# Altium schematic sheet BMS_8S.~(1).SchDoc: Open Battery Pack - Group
size A3; Author: Morgane Vallée; Revision: 1.0; SheetNumber: 2; SheetTotal: 3
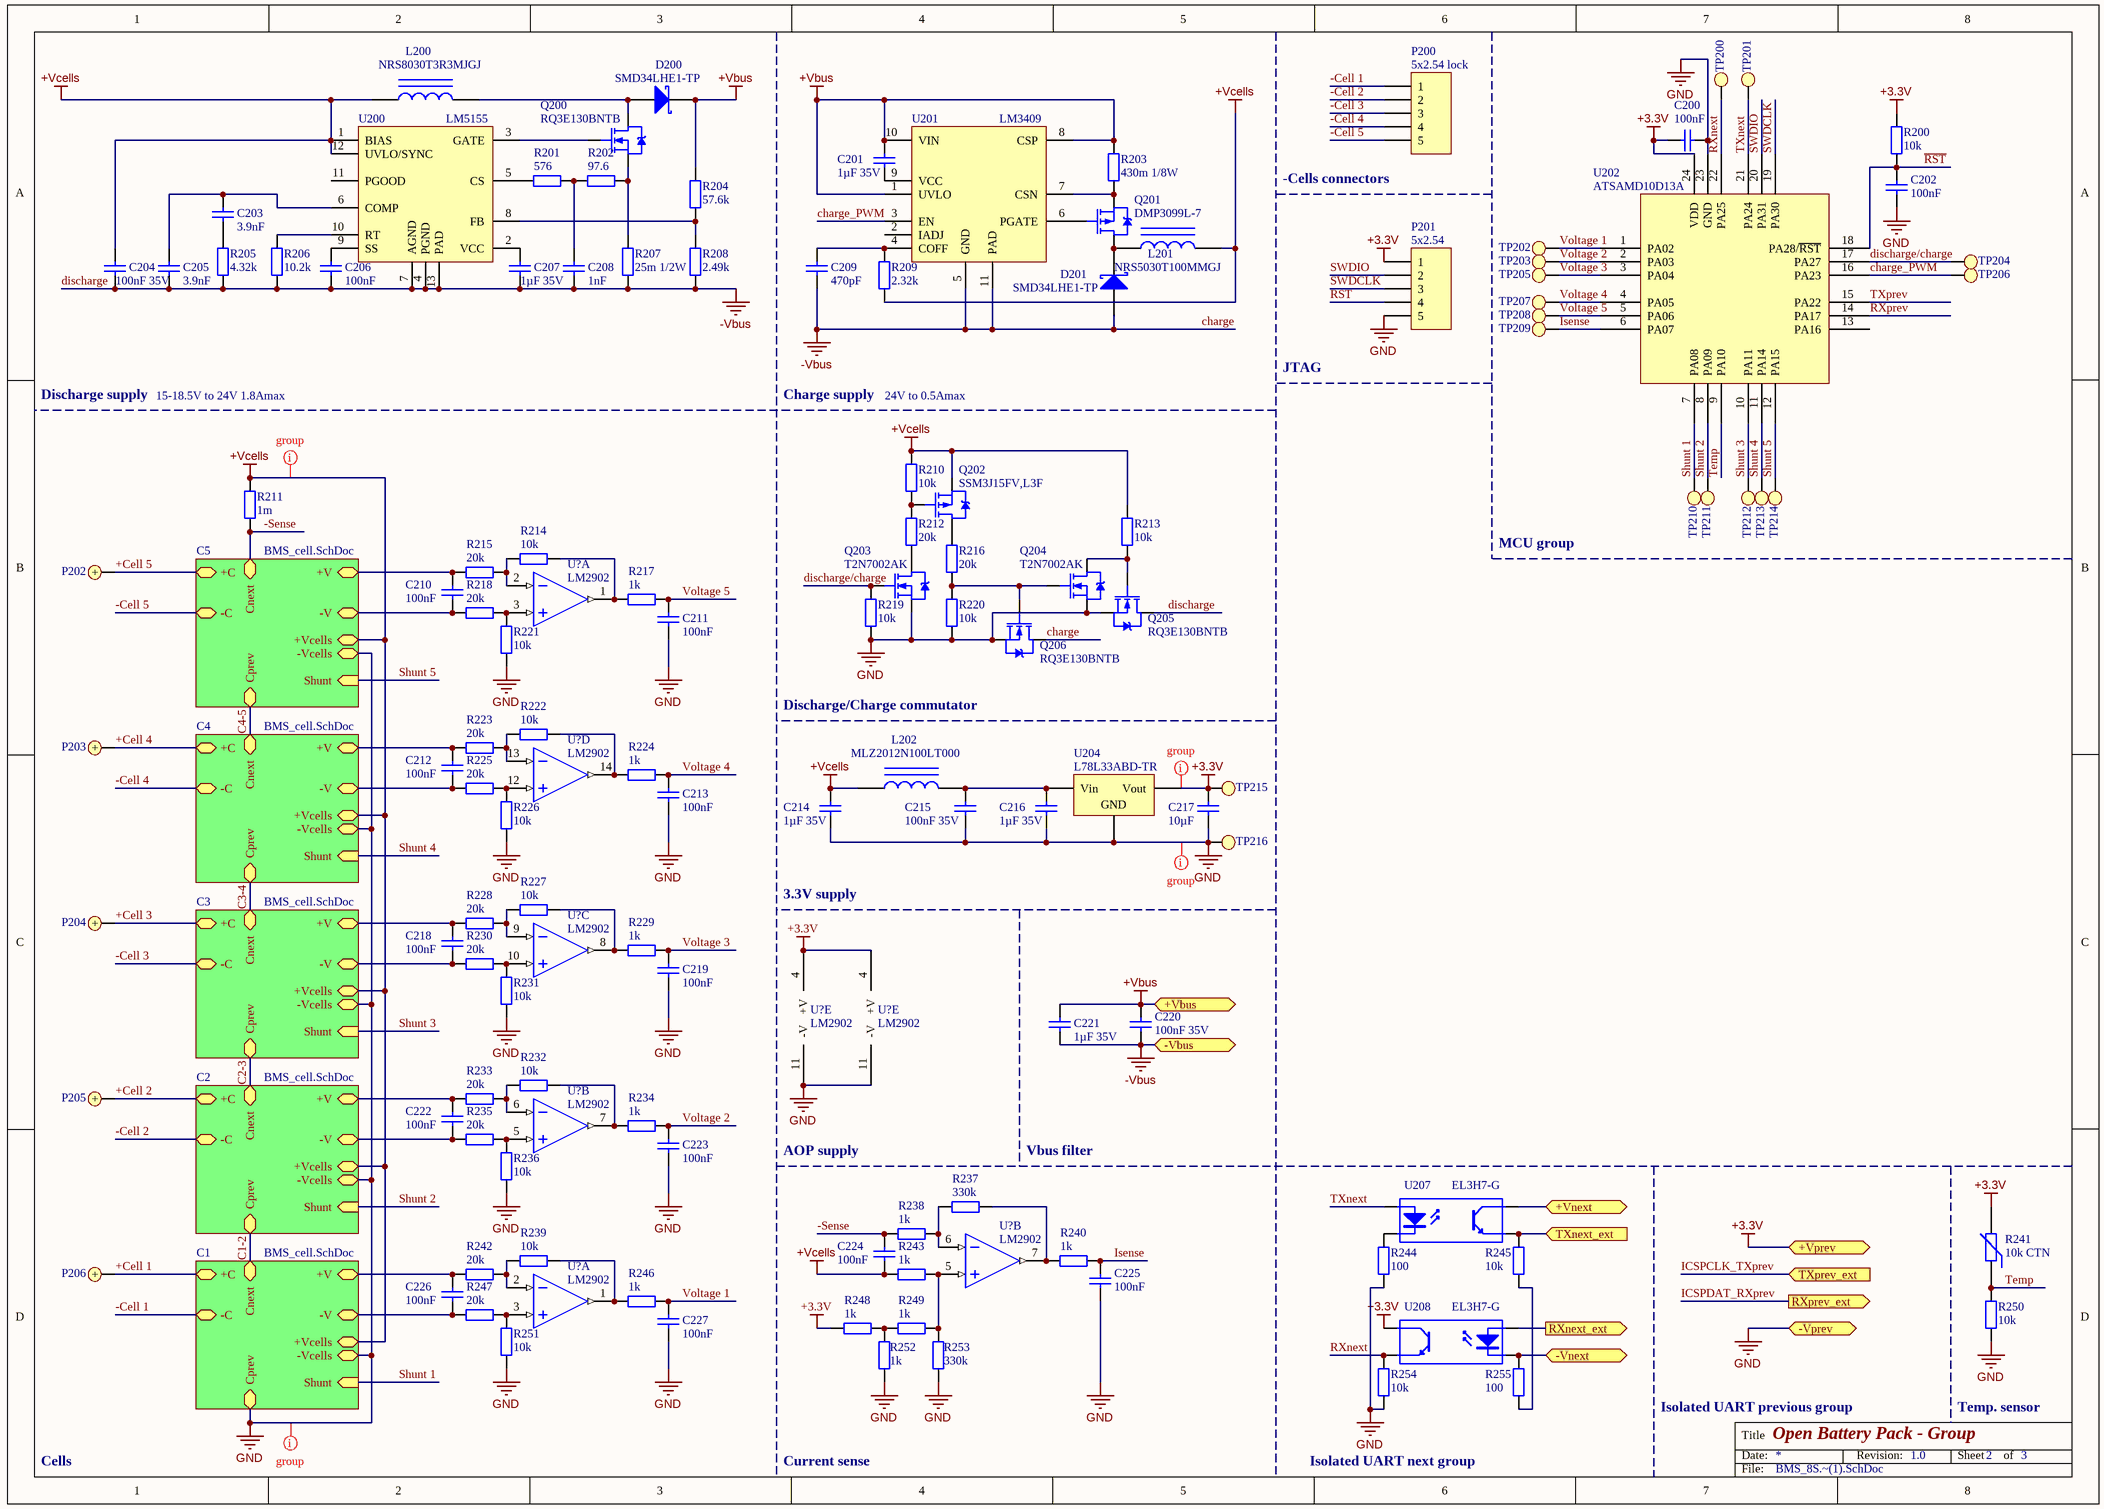
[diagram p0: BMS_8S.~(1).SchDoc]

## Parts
(Parts that share a designator on the sheet are numbered #1, #2 ... from top to bottom, then left to right.)
C200  100nF  [C0603]
C201  1µF 35V  [C0805]
C202  100nF  [C0603]
C203  3.9nF  [C0603]
C204  100nF 35V  [C0603]
C205  3.9nF  [C0603]
C206  100nF  [C0603]
C207  1µF 35V  [C0805]
C208  1nF  [C0603]
C209  470pF  [C0603]
C210  100nF  [C0603]
C211  100nF  [C0603]
C212  100nF  [C0603]
C213  100nF  [C0603]
C214  1µF 35V  [C0805]
C215  100nF 35V  [C0603]
C216  1µF 35V  [C0805]
C217  10µF  [C0603]
C218  100nF  [C0603]
C219  100nF  [C0603]
C220  100nF 35V  [C0603]
C221  1µF 35V  [C0805]
C222  100nF  [C0603]
C223  100nF  [C0603]
C224  100nF  [C0603]
C225  100nF  [C0603]
C226  100nF  [C0603]
C227  100nF  [C0603]
D200  SMD34LHE1-TP  [SOD-123H]
D201  SMD34LHE1-TP  [SOD-123H]
L200  NRS8030T3R3MJGJ  [SELF_SMD_8x8]
L201  NRS5030T100MMGJ  [SELF_SMD_4.9x4.9]
L202  MLZ2012N100LT000  [FER 0805/2012]
P200  5x2.54 lock  [MOLEX KK 0022272051]
P201  5x2.54  [HDR1X5]
P202  Bat+  [Keystone 241]  (value not drawn)
P203  Bat+  [Keystone 241]  (value not drawn)
P204  Bat+  [Keystone 241]  (value not drawn)
P205  Bat+  [Keystone 241]  (value not drawn)
P206  Bat+  [Keystone 241]  (value not drawn)
Q200  RQ3E130BNTB  [INFINEON PG-TSDSON-8]
Q201  DMP3099L-7  [DIODES SOT-23-3]
Q202  SSM3J15FV,L3F  [DIODES SOT-23-3]
Q203  T2N7002AK  [DIODES SOT-23-3]
Q204  T2N7002AK  [DIODES SOT-23-3]
Q205  RQ3E130BNTB  [INFINEON PG-TSDSON-8]
Q206  RQ3E130BNTB  [INFINEON PG-TSDSON-8]
R200  10k  [R0603]
R201  576  [R0603]
R202  97.6  [R0603]
R203  430m 1/8W  [R0603]
R204  57.6k  [R0603]
R205  4.32k  [R0603]
R206  10.2k  [R0603]
R207  25m 1/2W  [R1206]
R208  2.49k  [R0603]
R209  2.32k  [R0603]
R210  10k  [R0603]
R211  1m  [R1206]
R212  20k  [R0603]
R213  10k  [R0603]
R214  10k  [R0603]
R215  20k  [R0603]
R216  20k  [R0603]
R217  1k  [R0603]
R218  20k  [R0603]
R219  10k  [R0603]
R220  10k  [R0603]
R221  10k  [R0603]
R222  10k  [R0603]
R223  20k  [R0603]
R224  1k  [R0603]
R225  20k  [R0603]
R226  10k  [R0603]
R227  10k  [R0603]
R228  20k  [R0603]
R229  1k  [R0603]
R230  20k  [R0603]
R231  10k  [R0603]
R232  10k  [R0603]
R233  20k  [R0603]
R234  1k  [R0603]
R235  20k  [R0603]
R236  10k  [R0603]
R237  330k  [R0603]
R238  1k  [R0603]
R239  10k  [R0603]
R240  1k  [R0603]
R241  10k CTN  [NTC 0402/1005]
R242  20k  [R0603]
R243  1k  [R0603]
R244  100  [R0603]
R245  10k  [R0603]
R246  1k  [R0603]
R247  20k  [R0603]
R248  1k  [R0603]
R249  1k  [R0603]
R250  10k  [R0603]
R251  10k  [R0603]
R252  1k  [R0603]
R253  330k  [R0603]
R254  10k  [R0603]
R255  100  [R0603]
TP200  Test Point  [Test Point]  (value not drawn)
TP201  Test Point  [Test Point]  (value not drawn)
TP202  Test Point  [Test Point]  (value not drawn)
TP203  Test Point  [Test Point]  (value not drawn)
TP204  Test Point  [Test Point]  (value not drawn)
TP205  Test Point  [Test Point]  (value not drawn)
TP206  Test Point  [Test Point]  (value not drawn)
TP207  Test Point  [Test Point]  (value not drawn)
TP208  Test Point  [Test Point]  (value not drawn)
TP209  Test Point  [Test Point]  (value not drawn)
TP210  Test Point  [Test Point]  (value not drawn)
TP211  Test Point  [Test Point]  (value not drawn)
TP212  Test Point  [Test Point]  (value not drawn)
TP213  Test Point  [Test Point]  (value not drawn)
TP214  Test Point  [Test Point]  (value not drawn)
TP215  Test Point  [Test Point]  (value not drawn)
TP216  Test Point  [Test Point]  (value not drawn)
U200  LM5155  [TI WSON-12]
U201  LM3409  [TI MSOP-10 DGQ]
U202  ATSAMD10D13A  [SMSC QFN-24 4x4MM]
U204  L78L33ABD-TR  [ST SOIC-8N]
U207  EL3H7-G  [OPTO_EL3H7-G]
U208  EL3H7-G  [OPTO_EL3H7-G]
U?#1  LM2902  [Atmel SO-14 14S1]  (part A of 5)
U?#2  LM2902  [Atmel SO-14 14S1]  (part D of 5)
U?#3  LM2902  [Atmel SO-14 14S1]  (part C of 5)
U?#4  LM2902  [Atmel SO-14 14S1]  (part E of 5)
U?#5  LM2902  [Atmel SO-14 14S1]  (part E of 5)
U?#6  LM2902  [Atmel SO-14 14S1]  (part B of 5)
U?#7  LM2902  [Atmel SO-14 14S1]  (part B of 5)
U?#8  LM2902  [Atmel SO-14 14S1]  (part A of 5)

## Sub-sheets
C1 = BMS_cell.SchDoc: -C, -V, +C, +Vcells, Cnext, -Vcells, +V, Shunt (in), Cprev
C2 = BMS_cell.SchDoc: -C, -V, +C, +Vcells, Cnext, -Vcells, +V, Shunt (in), Cprev
C3 = BMS_cell.SchDoc: -C, -V, +C, +Vcells, Cnext, -Vcells, +V, Shunt (in), Cprev
C4 = BMS_cell.SchDoc: -C, -V, +C, +Vcells, Cnext, -Vcells, +V, Shunt (in), Cprev
C5 = BMS_cell.SchDoc: -C, -V, +C, +Vcells, Cnext, -Vcells, +V, Shunt (in), Cprev

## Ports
+Vbus, +Vnext, +Vprev, -Vbus, -Vnext, -Vprev, RXnext_ext (out), RXprev_ext (out), TXnext_ext (in), TXprev_ext (in)

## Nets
+3.3V: C200.2 C217.1 P201.1 R200.2 R241.2 R248.2 TP215.1 U202.24(VDD) U204.3(Vout) U208.4(C) U?#4.4(+V) U?#5.4(+V) ; port +Vprev
+Vbus: C201.1 C220.1 C221.1 D200.3(K) R203.2 R204.2 U201.1(UVLO) U201.8(CSP) U201.10(VIN) ; port +Vbus
+Vcells: C204.1 C214.1 C224.2 L200.1 L201.2 L202.1 Q202.2(S) R209.2 R210.2 R211.2 R213.2 R243.2 U200.1(BIAS) U200.12(UVLO/SYNC) ; sheet C1/+Vcells, sheet C2/+Vcells, sheet C3/+Vcells, sheet C4/+Vcells, sheet C5/+Vcells
charge: C204.2 C205.2 C206.2 C207.2 C208.2 C209.2 C220.2 C221.2 D201.1(A) Q205.3(D) Q206.3(D) R205.1 R206.1 R207.1 R208.1 U200.4(PGND) U200.7(AGND) U200.13(PAD) U201.5(GND) U201.11(PAD) ; port -Vbus  [also labelled -Vbus, discharge]
GND: C200.1 C202.1 C211.2 C213.2 C214.2 C215.2 C216.2 C217.2 C219.2 C223.2 C225.2 C227.2 P201.5 Q203.2(S) Q204.2(S) Q205.2(S) Q206.2(S) R219.1 R220.1 R221.2 R226.2 R231.2 R236.2 R244.1 R250.2 R251.2 R252.2 R253.1 R254.1 TP216.1 U202.23(GND) U204.2(GND) U?#4.11(-V) U?#5.11(-V) ; port -Vprev, sheet C1/-Vcells, sheet C1/Cprev, sheet C2/-Vcells, sheet C3/-Vcells, sheet C4/-Vcells, sheet C5/-Vcells
+Cell 1: P206.1 ; sheet C1/+C
+Cell 2: P205.1 ; sheet C2/+C
+Cell 3: P204.1 ; sheet C3/+C
+Cell 4: P203.1 ; sheet C4/+C
+Cell 5: P202.1 ; sheet C5/+C
+Vnext: U207.4(C) ; port +Vnext
-Cell 1: P200.1 ; sheet C1/-C
-Cell 2: P200.2 ; sheet C2/-C
-Cell 3: P200.3 ; sheet C3/-C
-Cell 4: P200.4 ; sheet C4/-C
-Cell 5: P200.5 ; sheet C5/-C
-Sense: C224.1 R211.1 R238.1 ; sheet C5/Cnext
-Vnext: R255.1 U208.2(K) ; port -Vnext
C1-2: sheet C1/Cnext, sheet C2/Cprev
C2-3: sheet C2/Cnext, sheet C3/Cprev
C3-4: sheet C3/Cnext, sheet C4/Cprev
C4-5: sheet C4/Cnext, sheet C5/Cprev
charge_PWM: TP206.1 U201.3(EN) U202.16(PA23)
discharge/charge: Q203.1(G) R219.2 TP204.1 U202.17(PA27)
Isense: C225.1 R240.1 TP209.1 U202.6(PA07)
~{RST}: C202.2 P201.4 R200.1 U202.18(PA28/~{RST})
RXnext: R254.2 TP200.1 U202.22(PA25) U208.3(E)
RXnext_ext: U208.1(A) ; port RXnext_ext
RXprev: U202.14(PA17)
Shunt 1: TP210.1 U202.7(PA08) ; sheet C1/Shunt
Shunt 2: TP211.1 U202.8(PA09) ; sheet C2/Shunt
Shunt 3: TP212.1 U202.10(PA11) ; sheet C3/Shunt
Shunt 4: TP213.1 U202.11(PA14) ; sheet C4/Shunt
Shunt 5: TP214.1 U202.12(PA15) ; sheet C5/Shunt
SWDCLK: P201.3 U202.19(PA30)
SWDIO: P201.2 U202.20(PA31)
Temp: R241.1 R250.1 U202.9(PA10)
TXnext: TP201.1 U202.21(PA24) U207.1(A)
TXnext_ext: R245.1 U207.3(E) ; port TXnext_ext
TXprev: U202.15(PA22)
Voltage 1: C227.1 R246.1 TP202.1 U202.1(PA02)
Voltage 2: C223.1 R234.1 TP203.1 U202.2(PA03)
Voltage 3: C219.1 R229.1 TP205.1 U202.3(PA04)
Voltage 4: C213.1 R224.1 TP207.1 U202.4(PA05)
Voltage 5: C211.1 R217.1 TP208.1 U202.5(PA06)
NetC201_2: C201.2 U201.9(VCC)
NetC203_1: C203.1 C205.1 U200.6(COMP)
NetC203_2: C203.2 R205.2
NetC206_1: C206.1 U200.9(SS)
NetC207_1: C207.1 U200.2(VCC)
NetC208_1: C208.1 R201.1 R202.2
NetC209_1: C209.1 R209.1 U201.4(COFF)
NetC210_1: C210.1 R215.1 ; sheet C5/+V
NetC210_2: C210.2 R218.2 ; sheet C5/-V
NetC212_1: C212.1 R223.1 ; sheet C4/+V
NetC212_2: C212.2 R225.2 ; sheet C4/-V
NetC215_1: C215.1 C216.1 L202.2 U204.1(Vin)
NetC218_1: C218.1 R228.1 ; sheet C3/+V
NetC218_2: C218.2 R230.2 ; sheet C3/-V
NetC222_1: C222.1 R233.1 ; sheet C2/+V
NetC222_2: C222.2 R235.2 ; sheet C2/-V
NetC226_1: C226.1 R242.1 ; sheet C1/+V
NetC226_2: C226.2 R247.2 ; sheet C1/-V
NetD200_1: D200.1(A) L200.2 Q200.3(D)
NetD201_3: D201.3(K) L201.1 Q201.3(D)
NetQ200_1: Q200.1(G) U200.3(GATE)
NetQ200_2: Q200.2(S) R202.1 R207.2
NetQ201_1: Q201.1(G) U201.6(PGATE)
NetQ201_2: Q201.2(S) R203.1 U201.7(CSN)
NetQ202_1: Q202.1(G) R210.1 R212.2
NetQ202_3: Q202.3(D) R216.2
NetQ203_3: Q203.3(D) R212.1
NetQ204_1: Q204.1(G) Q206.1(G) R216.1 R220.2
NetQ204_3: Q204.3(D) Q205.1(G) R213.1
NetR201_2: R201.2 U200.5(CS)
NetR204_1: R204.1 R208.2 U200.8(FB)
NetR206_2: R206.2 U200.10(RT)
NetR214_1: R214.1 R215.2 U?#1.2(IN-)
NetR214_2: R214.2 R217.2 U?#1.1(OUT)
NetR218_1: R218.1 R221.1 U?#1.3(IN+)
NetR222_1: R222.1 R223.2 U?#2.13(IN-)
NetR222_2: R222.2 R224.2 U?#2.14(OUT)
NetR225_1: R225.1 R226.1 U?#2.12(IN+)
NetR227_1: R227.1 R228.2 U?#3.9(IN-)
NetR227_2: R227.2 R229.2 U?#3.8(OUT)
NetR230_1: R230.1 R231.1 U?#3.10(IN+)
NetR232_1: R232.1 R233.2 U?#6.6(IN-)
NetR232_2: R232.2 R234.2 U?#6.7(OUT)
NetR235_1: R235.1 R236.1 U?#6.5(IN+)
NetR237_1: R237.1 R240.2 U?#7.7(OUT)
NetR237_2: R237.2 R238.2 U?#7.6(IN-)
NetR239_1: R239.1 R242.2 U?#8.2(IN-)
NetR239_2: R239.2 R246.2 U?#8.1(OUT)
NetR243_1: R243.1 R249.1 R253.2 U?#7.5(IN+)
NetR244_2: R244.2 U207.2(K)
NetR245_2: R245.2 R255.2
NetR247_1: R247.1 R251.1 U?#8.3(IN+)
NetR248_1: R248.1 R249.2 R252.1

Not connected (* = marked no-connect by the designer): U200 11(PGOOD); U201 2(IADJ); U202 13(PA16)

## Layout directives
net class Group: +3.3V, +Vcells, GND

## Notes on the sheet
- (near P200) -Cells connectors
- JTAG
- Discharge supply
- 15-18.5V to 24V 1.8Amax
- Charge supply
- 24V to 0.5Amax
- MCU group
- Discharge/Charge commutator
- 3.3V supply
- AOP supply
- Vbus filter
- Isolated UART previous group
- Temp. sensor
- Cells
- Current sense
- Isolated UART next group

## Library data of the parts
C200-C227 = Cap: Capacitor
D200 D201 = Diode BAT17
L200-L202 = Inductor Iron: Magnetic-Core Inductor
P200 P201 = Header 5: Header, 5-Pin
P202-P206 = Bat+: Battery contact +
Q200 Q203-Q206 = MOSFET_N
Q201 Q202 = MOSFET_P
R200-R240 R242-R255 = Res2: Resistor
R241 = Res Varistor: Varistor (Voltage-Sensitive Resistor)
U200 = LM5155: 2.2-MHz Wide Input Nonsynchronous Boost, SEPIC, Flyback Controller
U201 = LM3409: P-FET Buck Controller for High-Power LED Drivers
U204 = Volt Reg: Voltage Regulator; pin to pad: 1>8 2>2+3+6+7 3>1
U207 U208 = Optoisolator1: 4-Pin Phototransistor Optocoupler
U?#1-U?#8 = LM2902: Low-power quad operational amplifiers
